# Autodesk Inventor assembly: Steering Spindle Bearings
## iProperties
Length Units: 11269
Angle Units: 11279
Time Units: 11290
Mass Units: 11283
Shininess: 3
Angle Display Precision: 2
Document Length Units: 11269
Document Angle Units: 11279
Document Time Units: 11290
Document Mass Units: 11283
Document Length Units Precision: 3
Document Angle Units Precision: 2
Compacted: True
Created: 2001-08
Part Number: Steering Spindle Bearings
Document SubType Name: Assembly
Designer: Martin Budgell
Density: 0.0
Volumn: 0.0
Area: 0.0
PropertySet Name: Model Information
Control State: 0
Master: False
Checked Out: False
Author: Martin Budgell
